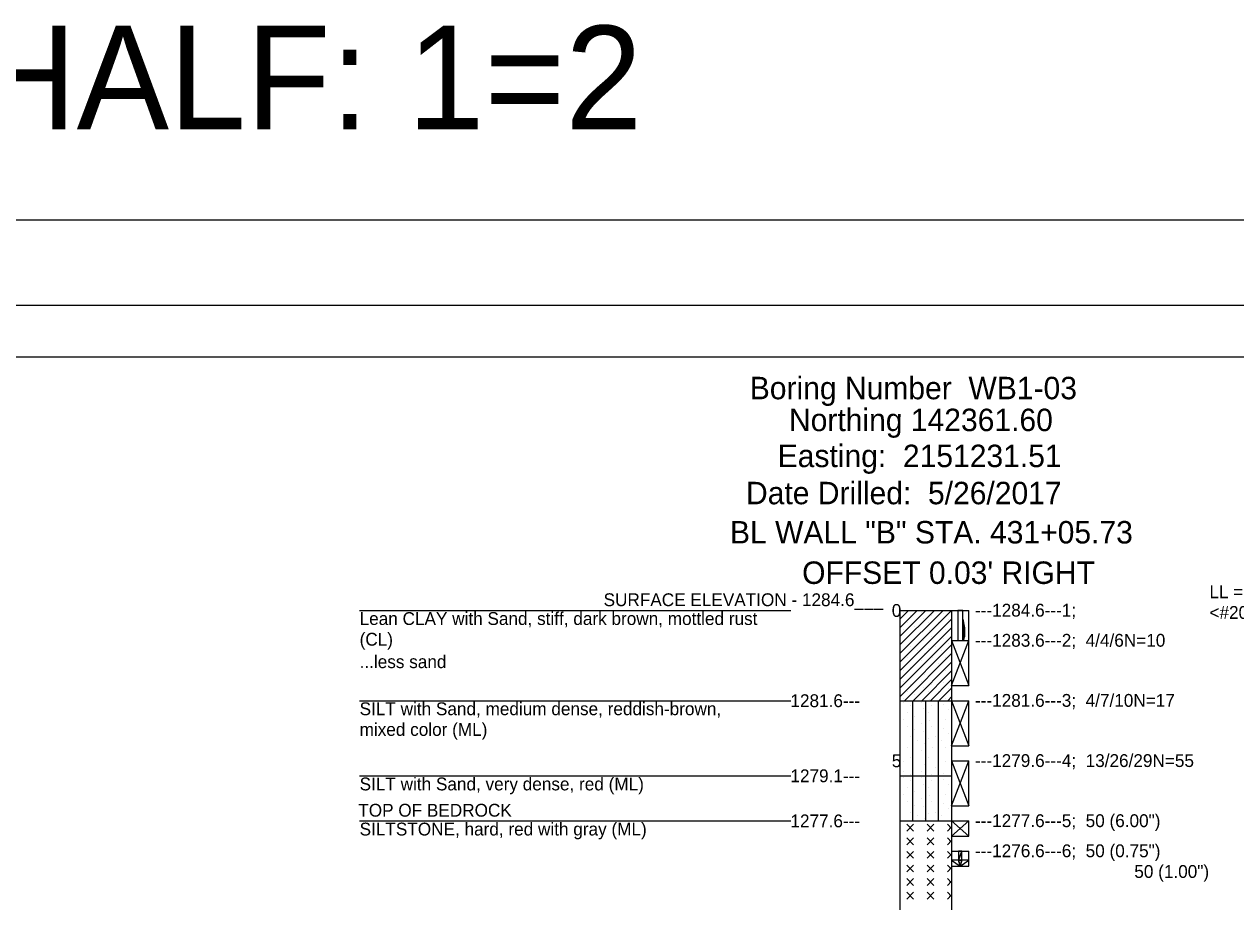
# Model space of a CAD drawing. Extents: x 7 to 126, y 24 to 56.
# Drawn here: x 66.46 to 78.17, y 47.38 to 55.86 of the extents above; entities that cross this region are included whole.
import ezdxf

# ---------------------------------------------------------------- set-up
doc = ezdxf.new("R2010")
doc.units = 0
for name, color, linetype in [('S', 7, 'Continuous'), ('SHT_Plot_Shape_Full', 7, 'Continuous'), ('SHT_Plot_Shape_Half', 7, 'Continuous'), ('SHT_Sheet_Border', 7, 'Continuous')]:
    doc.layers.add(name, color=color, linetype=linetype)

# ---------------------------------------------------------------- blocks, each defined once
blk = doc.blocks.new('POINT_DISPLAY')
blk.add_line((0, 0), (0, 0))

msp = doc.modelspace()

# ---------------------------------------------------------------- linework, layer by layer
for points in [[(69.702, 50.194), (73.869, 50.194)], [(74.921, 50.111), (75.005, 50.194)], [(74.921, 50.028), (75.088, 50.194)], [(74.921, 49.944), (75.171, 50.194)], [(74.921, 49.861), (75.255, 50.194)], [(74.921, 49.778), (75.338, 50.194)], [(74.921, 49.694), (75.421, 50.194)], [(74.921, 50.194), (74.921, 39.148)], [(74.921, 50.194), (75.421, 50.194)], [(74.921, 49.611), (75.421, 50.111)], [(75.421, 50.194), (75.588, 50.194)], [(75.421, 50.194), (75.421, 39.148)], [(75.588, 49.904), (75.588, 50.194)], [(74.921, 49.528), (75.421, 50.028)], [(74.921, 49.444), (75.421, 49.944)], [(74.921, 49.361), (75.421, 49.861)], [(75.421, 49.904), (75.588, 49.904)], [(75.421, 49.904), (75.588, 49.468)], [(75.421, 49.468), (75.588, 49.904)], [(75.421, 49.904), (75.588, 49.904)], [(75.588, 49.468), (75.588, 49.904)], [(74.966, 49.322), (75.421, 49.778)], [(75.049, 49.322), (75.421, 49.694)], [(75.133, 49.322), (75.421, 49.611)], [(75.216, 49.322), (75.421, 49.528)], [(75.299, 49.322), (75.421, 49.444)], [(75.421, 49.468), (75.588, 49.468)], [(69.702, 49.322), (73.869, 49.322)], [(74.921, 49.322), (75.421, 49.322)], [(75.046, 48.596), (75.046, 49.322)], [(75.171, 48.596), (75.171, 49.322)], [(75.296, 48.596), (75.296, 49.322)], [(75.383, 49.322), (75.421, 49.361)], [(75.421, 49.322), (75.588, 48.886)], [(75.421, 48.886), (75.588, 49.322)], [(75.421, 49.322), (75.588, 49.322)], [(75.588, 48.886), (75.588, 49.322)], [(75.421, 48.886), (75.588, 48.886)], [(75.421, 48.741), (75.588, 48.305)], [(75.421, 48.305), (75.588, 48.741)], [(75.421, 48.741), (75.588, 48.741)], [(75.588, 48.305), (75.588, 48.741)], [(69.702, 48.596), (73.869, 48.596)], [(74.921, 48.596), (75.421, 48.596)], [(75.046, 48.16), (75.046, 48.596)], [(75.171, 48.16), (75.171, 48.596)], [(75.296, 48.16), (75.296, 48.596)], [(75.421, 48.305), (75.588, 48.305)], [(69.702, 48.16), (73.869, 48.16)], [(74.921, 48.16), (75.421, 48.16)], [(75.053, 48.127), (74.987, 48.061)], [(74.987, 48.127), (75.053, 48.061)], [(75.25, 48.127), (75.184, 48.061)], [(75.184, 48.127), (75.25, 48.061)], [(75.381, 48.127), (75.421, 48.086)], [(75.421, 48.16), (75.588, 48.014)], [(75.421, 48.014), (75.588, 48.16)], [(75.421, 48.16), (75.588, 48.16)], [(75.588, 48.014), (75.588, 48.16)], [(75.053, 47.995), (74.987, 47.93)], [(74.987, 47.995), (75.053, 47.93)], [(75.25, 47.995), (75.184, 47.93)], [(75.184, 47.995), (75.25, 47.93)], [(75.421, 48.102), (75.381, 48.061)], [(75.381, 47.995), (75.421, 47.955)], [(75.421, 48.014), (75.588, 48.014)], [(75.421, 47.971), (75.381, 47.93)], [(75.053, 47.864), (74.987, 47.799)], [(74.987, 47.864), (75.053, 47.799)], [(75.25, 47.864), (75.184, 47.799)], [(75.184, 47.864), (75.25, 47.799)], [(75.381, 47.864), (75.421, 47.824)], [(75.421, 47.839), (75.381, 47.799)], [(75.421, 47.869), (75.588, 47.869)], [(75.588, 47.723), (75.588, 47.869)], [(75.053, 47.733), (74.987, 47.667)], [(74.987, 47.733), (75.053, 47.667)], [(75.25, 47.733), (75.184, 47.667)], [(75.184, 47.733), (75.25, 47.667)], [(75.381, 47.733), (75.421, 47.692)], [(75.421, 47.708), (75.381, 47.667)], [(75.421, 47.723), (75.588, 47.723)], [(75.053, 47.602), (74.987, 47.536)], [(74.987, 47.602), (75.053, 47.536)], [(75.25, 47.602), (75.184, 47.536)], [(75.184, 47.602), (75.25, 47.536)], [(75.381, 47.602), (75.421, 47.561)], [(75.421, 47.577), (75.381, 47.536)], [(75.053, 47.471), (74.987, 47.405)], [(74.987, 47.471), (75.053, 47.405)], [(75.25, 47.471), (75.184, 47.405)], [(75.184, 47.471), (75.25, 47.405)], [(75.381, 47.471), (75.421, 47.43)], [(75.421, 47.446), (75.381, 47.405)]]:
    msp.add_lwpolyline(points)
for points in [[(75.48, 50.194), (75.48, 49.904), (75.53, 49.904), (75.53, 50.194)], [(75.544, 50.028), (75.538, 50.069), (75.53, 50.109), (75.544, 50.028)], [(75.53, 50.109), (75.53, 49.904), (75.544, 50.028), (75.53, 50.109)], [(75.53, 49.904), (75.544, 49.944), (75.544, 50.028), (75.53, 49.904)], [(75.544, 49.944), (75.546, 49.986), (75.544, 50.028), (75.544, 49.944)], [(75.53, 49.904), (75.539, 49.904), (75.544, 49.944), (75.53, 49.904)], [(75.488, 47.782), (75.421, 47.782), (75.505, 47.723), (75.488, 47.782)], [(75.488, 47.782), (75.521, 47.782), (75.521, 47.869), (75.488, 47.782)], [(75.488, 47.782), (75.521, 47.869), (75.488, 47.869), (75.488, 47.782)], [(75.488, 47.782), (75.505, 47.723), (75.521, 47.782), (75.488, 47.782)], [(75.505, 47.723), (75.588, 47.782), (75.521, 47.782), (75.505, 47.723)]]:
    msp.add_lwpolyline(points, close=True)
at = {"layer": 'SHT_Plot_Shape_Full'}
msp.add_lwpolyline([(48.302, 53.971), (84.302, 53.971), (84.302, 29.971), (48.302, 29.971)], close=True, dxfattribs=at)
at = {"layer": 'SHT_Plot_Shape_Half'}
msp.add_lwpolyline([(49.939, 53.146), (83.939, 53.146), (83.939, 31.146), (49.939, 31.146)], close=True, dxfattribs=at)
at = {"layer": 'SHT_Sheet_Border'}
msp.add_lwpolyline([(51.889, 52.646), (83.389, 52.646), (83.389, 31.646), (51.889, 31.646)], close=True, dxfattribs=at)

# ---------------------------------------------------------------- block references
at = {"xscale": 0.01, "yscale": 0.01}
for p in [(74.927, 50.111), (74.961, 50.178), (75.027, 50.144), (75.127, 50.178), (75.15, 50.114), (75.227, 50.144), (75.347, 50.161), (75.394, 50.111), (74.961, 50.011), (74.994, 50.078), (75.061, 50.044), (75.127, 49.978), (75.194, 50.078), (75.211, 50.002), (75.294, 50.078), (75.361, 50.011), (74.927, 49.878), (74.994, 49.944), (75.061, 49.911), (75.146, 49.9), (75.227, 49.944), (75.345, 49.926), (75.394, 49.878), (74.994, 49.744), (75.027, 49.844), (75.094, 49.811), (75.161, 49.778), (75.197, 49.831), (75.24, 49.744), (75.261, 49.844), (75.327, 49.811), (75.361, 49.744), (74.927, 49.678), (75.027, 49.644), (75.127, 49.711), (75.194, 49.644), (75.294, 49.678), (74.961, 49.611), (74.961, 49.511), (75.127, 49.511), (75.161, 49.578), (75.261, 49.544), (75.361, 49.611), (74.927, 49.444), (74.994, 49.411), (75.027, 49.478), (75.15, 49.447), (75.194, 49.411), (75.227, 49.478), (75.294, 49.411), (75.347, 49.494), (75.394, 49.444), (74.961, 49.344), (74.961, 49.306), (75.061, 49.378), (75.127, 49.306), (75.211, 49.335), (75.347, 49.289), (75.361, 49.344), (74.927, 49.239), (74.994, 49.206), (75.027, 49.272), (75.061, 49.172), (75.15, 49.242), (75.194, 49.206), (75.227, 49.272), (75.294, 49.206), (75.394, 49.239), (74.961, 49.139), (74.994, 49.072), (75.127, 49.106), (75.211, 49.13), (75.227, 49.072), (75.345, 49.054), (75.361, 49.139), (74.927, 49.006), (75.027, 48.972), (75.061, 49.039), (75.094, 48.939), (75.146, 49.028), (75.197, 48.959), (75.261, 48.972), (75.327, 48.939), (75.394, 49.006), (74.994, 48.872), (75.127, 48.839), (75.161, 48.906), (75.24, 48.872), (75.361, 48.872), (74.927, 48.806), (74.961, 48.739), (75.027, 48.772), (75.161, 48.706), (75.194, 48.772), (75.294, 48.806), (75.361, 48.739), (74.961, 48.639), (74.961, 48.579), (75.027, 48.606), (75.127, 48.639), (75.127, 48.579), (75.227, 48.606), (75.261, 48.672), (75.347, 48.622), (74.927, 48.512), (74.994, 48.479), (75.027, 48.546), (75.15, 48.515), (75.194, 48.479), (75.227, 48.546), (75.294, 48.479), (75.347, 48.562), (75.394, 48.512), (74.961, 48.412), (74.994, 48.346), (75.061, 48.446), (75.127, 48.379), (75.211, 48.403), (75.227, 48.346), (75.361, 48.412), (74.927, 48.279), (75.027, 48.246), (75.061, 48.312), (75.146, 48.302), (75.197, 48.232), (75.261, 48.246), (75.345, 48.327), (75.394, 48.279), (75.094, 48.212), (75.161, 48.179), (75.327, 48.212)]:
    msp.add_blockref('POINT_DISPLAY', p, dxfattribs=at)

# ---------------------------------------------------------------- texts
for s, height, p in [('Boring Number  WB1-03', 0.217, (73.471, 52.236)), ('Northing 142361.60', 0.217, (73.85, 51.928)), ('Easting:  2151231.51', 0.217, (73.741, 51.58)), ('Date Drilled:  5/26/2017', 0.217, (73.435, 51.221)), ('BL WALL "B" STA. 431+05.73', 0.217, (73.28, 50.842)), ("OFFSET 0.03' RIGHT", 0.217, (73.977, 50.451)), ('SURFACE ELEVATION - 1284.6___', 0.124, (72.059, 50.236)), ('LL = 38; PL = 18;', 0.124, (77.912, 50.313)), ('0', 0.124, (74.843, 50.132)), ('---1284.6---1;', 0.124, (75.647, 50.135)), ('<#200=80.1%; w%=21%', 0.124, (77.912, 50.113)), ('Lean CLAY with Sand, stiff, dark brown, mottled rust', 0.124, (69.702, 50.054)), ('(CL)', 0.124, (69.702, 49.854)), ('---1283.6---2;  4/4/6N=10', 0.124, (75.647, 49.844)), ('...less sand', 0.124, (69.702, 49.637)), ('---1281.6---3;  4/7/10N=17', 0.124, (75.647, 49.263)), ('SILT with Sand, medium dense, reddish-brown,', 0.124, (69.702, 49.182)), ('1281.6---', 0.124, (73.864, 49.26)), ('mixed color (ML)', 0.124, (69.702, 48.982)), ('---1279.6---4;  13/26/29N=55', 0.124, (75.647, 48.681)), ('5', 0.124, (74.843, 48.679)), ('SILT with Sand, very dense, red (ML)', 0.124, (69.702, 48.455)), ('1279.1---', 0.124, (73.864, 48.534)), ('TOP OF BEDROCK', 0.124, (69.689, 48.201)), ('1277.6---', 0.124, (73.864, 48.098)), ('---1277.6---5;  50 (6.00")', 0.124, (75.647, 48.1)), ('SILTSTONE, hard, red with gray (ML)', 0.124, (69.702, 48.019)), ('---1276.6---6;  50 (0.75")', 0.124, (75.647, 47.809)), ('50 (1.00")', 0.124, (77.186, 47.609))]:
    msp.add_text(s, height=height).set_placement(p)
at = {"layer": 'S'}
msp.add_text('FULL: 1=1   HALF: 1=2', height=1, dxfattribs=at).set_placement((58.607, 54.847))

doc.saveas('drawing.dxf')
